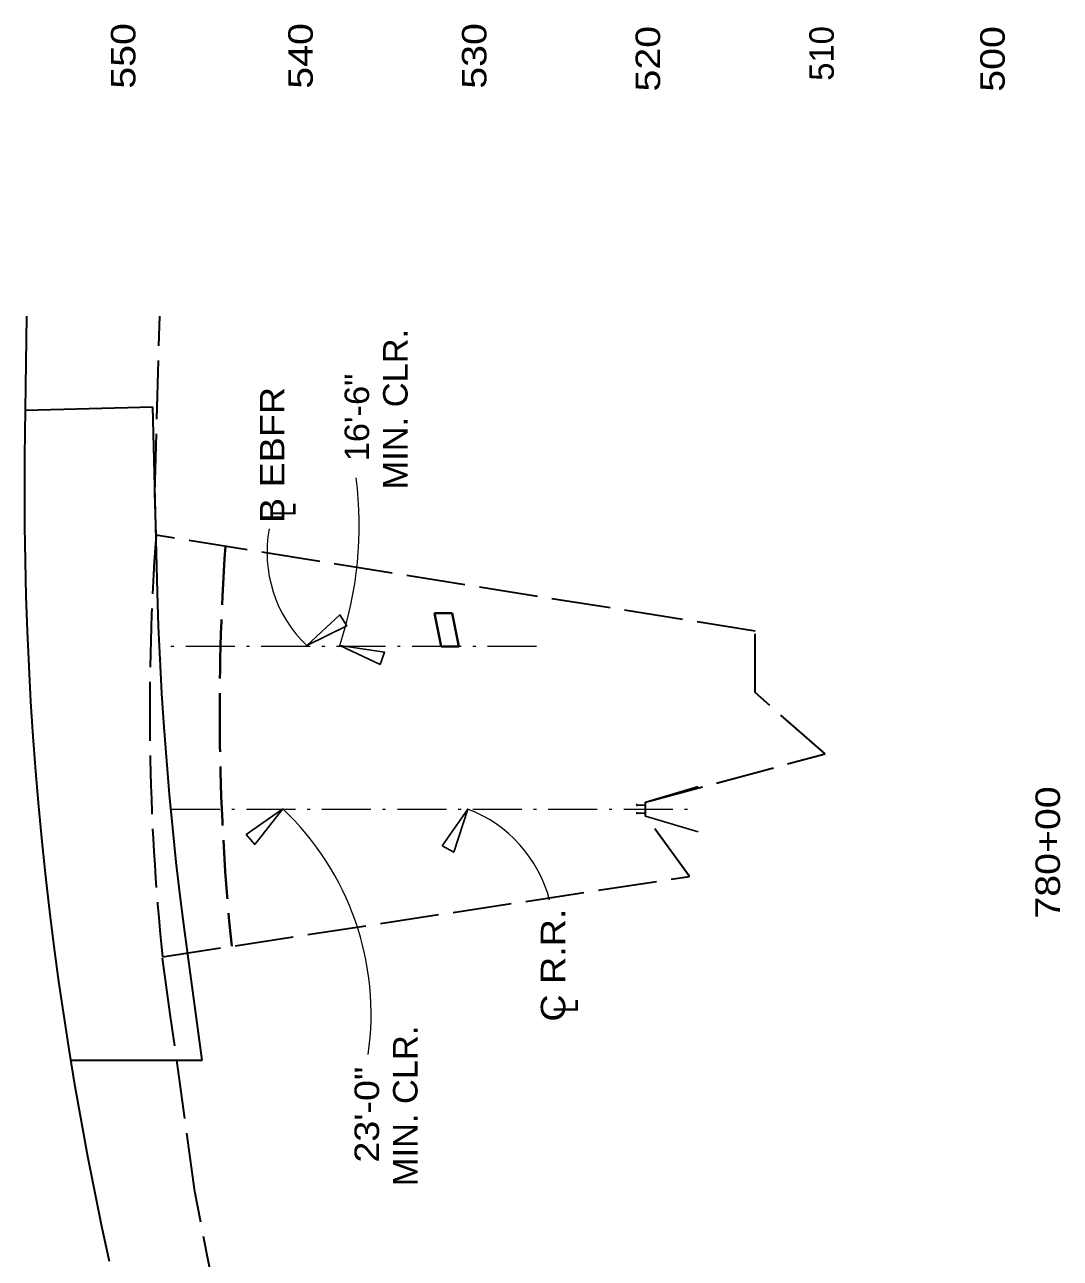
# Model space of a CAD drawing. Extents: x 2363427 to 2368559, y 6957299 to 6980140.
# Drawn here: x 2366256 to 2366848, y 6978618 to 6979323 of the extents above; entities that cross this region are included whole.
import ezdxf
from ezdxf.enums import TextEntityAlignment as Align

# ---------------------------------------------------------------- set-up
doc = ezdxf.new("R2010")
doc.units = 0
doc.header["$LTSCALE"] = 5.6
doc.linetypes.add('DOT_DASHED', pattern=[7.7, 5, -1.2, 0.3, -1.2])
doc.linetypes.add('LONG_DASHED', pattern=[7.5, 6, -1.5])
doc.layers.add('44', color=7, linetype='Continuous', lineweight=13)
doc.layers.add('61', color=7, linetype='Continuous', lineweight=25)

msp = doc.modelspace()

# ---------------------------------------------------------------- linework, layer by layer
at = {"layer": '44', "lineweight": 35}
for p, q in [((2366329.134, 6979104.03), (2366256.401, 6979102.212)), ((2366282.027, 6978731.013), (2366357.26, 6978731.013))]:
    msp.add_line(p, q, dxfattribs=at)
for points in [[(2366304.305, 6978615.99), (2366300.005, 6978635.99), (2366295.906, 6978655.99), (2366292.005, 6978675.99), (2366288.306, 6978695.991), (2366284.806, 6978715.991), (2366281.505, 6978735.991), (2366278.405, 6978755.991), (2366275.505, 6978775.99), (2366272.806, 6978795.99), (2366270.306, 6978815.99), (2366268.006, 6978835.99), (2366265.906, 6978855.99), (2366264.006, 6978875.99), (2366262.307, 6978895.99), (2366260.806, 6978915.99), (2366259.506, 6978935.99), (2366258.407, 6978955.99), (2366258.405, 6978956.024), (2366257.506, 6978976.024), (2366256.806, 6978996.023), (2366256.306, 6979016.023), (2366256.007, 6979036.023), (2366255.907, 6979056.023), (2366256.007, 6979076.023), (2366257.211, 6979156.033)], [(2366357.26, 6978731.013), (2366347.184, 6978805.658), (2366344.776, 6978824.927), (2366342.56, 6978844.192), (2366340.538, 6978863.453), (2366338.708, 6978882.711), (2366337.072, 6978901.969), (2366335.628, 6978921.227), (2366334.376, 6978940.48), (2366333.29, 6978960.25), (2366333.31, 6978959.91), (2366332.451, 6978979.02), (2366331.777, 6978998.273), (2366329.134, 6979104.03)]]:
    msp.add_lwpolyline(points, dxfattribs=at)
at = {"layer": '44', "linetype": 'LONG_DASHED', "lineweight": 35}
msp.add_lwpolyline([(2366372.719, 6978556.006), (2366353.119, 6978656.01), (2366339.318, 6978756.015), (2366334.626, 6978790.016), (2366635.731, 6978836.018), (2366610.73, 6978870.42), (2366610.73, 6978878.42), (2366713.335, 6978906.021), (2366673.333, 6978941.023), (2366673.333, 6978976.025), (2366330.958, 6979031.027), (2366330.278, 6979055.242), (2366333.118, 6979156.033)], dxfattribs=at)
msp.add_arc((2367703.521, 6978931.384), 1376.176, 175.84782, 185.89612, dxfattribs=at)
at = {"layer": '61', "lineweight": 40}
for p, q in [((2366493.825, 6978967.424), (2366490.025, 6978986.425)), ((2366490.025, 6978986.425), (2366500.223, 6978986.425)), ((2366504.023, 6978967.424), (2366500.223, 6978986.425)), ((2366493.825, 6978967.424), (2366504.023, 6978967.424))]:
    msp.add_line(p, q, dxfattribs=at)
at = {"layer": '61', "linetype": 'DOT_DASHED', "lineweight": 13}
for p, q in [((2366548.384, 6978967.424), (2366332.857, 6978967.424)), ((2366339.496, 6978874.42), (2366638.436, 6978874.42))]:
    msp.add_line(p, q, dxfattribs=at)
at = {"layer": '61'}
for p, q in [((2366610.73, 6978878.42), (2366640.732, 6978887.421)), ((2366610.73, 6978878.42), (2366610.73, 6978870.42)), ((2366605.73, 6978876.77), (2366610.73, 6978876.77)), ((2366605.73, 6978872.07), (2366610.73, 6978872.07)), ((2366640.732, 6978861.419), (2366610.73, 6978870.42))]:
    msp.add_line(p, q, dxfattribs=at)
at = {"layer": '61', "lineweight": 13}
for p, q in [((2366605.73, 6978876.77), (2366605.73, 6978877.366)), ((2366605.73, 6978876.77), (2366605.73, 6978876.186)), ((2366605.73, 6978872.07), (2366605.73, 6978872.591)), ((2366605.73, 6978872.07), (2366605.73, 6978871.468))]:
    msp.add_line(p, q, dxfattribs=at)
at = {"layer": '61'}
for points in [[(2366440.054, 6978979.081), (2366417.056, 6978967.862), (2366436.013, 6978985.372)], [(2366459.081, 6978957.015), (2366435.906, 6978967.862), (2366461.438, 6978964.112)], [(2366382.428, 6978859.848), (2366403.346, 6978874.585), (2366387.42, 6978854.281)], [(2366494.45, 6978853.407), (2366509.051, 6978874.42), (2366501.048, 6978849.887)]]:
    msp.add_lwpolyline(points, close=True, dxfattribs=at)
at = {"layer": '61', "lineweight": 13}
for centre, radius, start, end in [((2366230.09, 6979036.488), 216.956, 341.55996, 7.20711), ((2366468.195, 6979021.086), 73.811, 169.44177, 226.14454), ((2366292.678, 6978757.401), 161.181, 351.73857, 46.63823), ((2366482.229, 6978803.211), 76.093, 14.59353, 69.3604)]:
    msp.add_arc(centre, radius, start, end, dxfattribs=at)
at = {"layer": '61', "linetype": 'LONG_DASHED', "lineweight": 40}
msp.add_arc((2367703.521, 6978931.384), 1336.174, 175.99714, 185.81252, dxfattribs=at)

# ---------------------------------------------------------------- texts
at = {"layer": '44', "width": 1.2}
for s, p in [('550', (2366319.19, 6979323.535)), ('540', (2366420.522, 6979323.535)), ('530', (2366519.768, 6979323.536)), ('520', (2366619.015, 6979321.939)), ('500', (2366815.907, 6979321.828))]:
    msp.add_text(s, height=14, rotation=90, dxfattribs=at).set_placement(p, align=Align.RIGHT)
at = {"layer": '44'}
msp.add_text('510', height=14, rotation=90, dxfattribs=at).set_placement((2366718.261, 6979321.827), align=Align.RIGHT)
at = {"layer": '44', "width": 1.2}
msp.add_text('780+00', height=14, rotation=90, dxfattribs=at).set_placement((2366847.493, 6978849.656), align=Align.CENTER)
at = {"layer": '61'}
for s, width, p in [('MIN. CLR.', 1.05, (2366474.71, 6979102.957)), ('16\'-6" ', 1.05, (2366452.709, 6979100.952)), ('B EBFR', 1.15, (2366404.321, 6979076.781)), ('L', 0.75, (2366410.799, 6979045.53)), ('C R.R.', 1.15, (2366564.828, 6978785.288)), ('L', 0.75, (2366572.143, 6978761.946)), ('MIN. CLR.', 1.05, (2366480.396, 6978704.837)), ('23\'-0" ', 1.15, (2366458.395, 6978702.833))]:
    msp.add_text(s, height=14, rotation=90, dxfattribs=dict(at, width=width)).set_placement(p, align=Align.CENTER)

doc.saveas('drawing.dxf')
